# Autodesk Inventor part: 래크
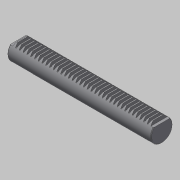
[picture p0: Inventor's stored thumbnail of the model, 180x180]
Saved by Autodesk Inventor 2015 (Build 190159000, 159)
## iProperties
Created: 2019-06
Part Number: 래크
Material: 스테인리스강
Document SubType Name: Modeling
Designer: mduedu
Density: 1 g/cm^3
Appearance: 기본값
Author: mduedu
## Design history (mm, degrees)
sketch "스케치1"
  geometry: L1 (0, 0)-(240, 0); L2 (240, 0)-(240, 34); L3 (240, 34)-(0, 34); L4 (0, 34)-(0, 0)
  constraints: 8 end point, 2 parallel, 1 horizontal, 1 perpendicular
  dimensions: "d0" = 240 distance of L1.start L1.end; "d1" = 34 distance of L1.end L2.end
extrude "돌출1" new body sketch "스케치1" stored distance "d2" = 36; taper "d3" = 0 deg
sketch "스케치2"
  geometry: L1 (0, 0)-(240, 0) reference; L2 (240, 0)-(240, 34) reference; L3 (240, 34)-(0, 34) reference; L4 (0, 34)-(0, 0) reference; L5 (9.44, 29.5)-(10.76, 29.5); L6 (12.398, 34)-(7.802, 34); L7 (10.1, 34)-(10.1, 29.5); L8 (7.802, 34)-(9.44, 29.5); L9 (12.398, 34)-(10.76, 29.5); L10 (8.53, 32)-(11.67, 32); 1 further point
  constraints: 12 end point, 2 midpoint, 2 point on line, 1 collinear, 1 horizontal, 1 parallel, 1 perpendicular, 1 symmetric about line
  dimensions: "d4" = 20 deg angle of L9 L7; "d5" = 2 distance between parallel lines of L10 L6; "d7" = 4.5 distance between parallel lines of L5 L6 (= 2.25 x d5); "d8" = 3.14 distance of L10.start L10.end; "d9" = 10.1 distance between parallel lines of L4 L7
extrude "돌출2" cut sketch "스케치2" stored distance "d10" = 36; taper "d11" = 0 deg
sketch "스케치3"
  geometry: L1 (235.52, 29.5)-(233.882, 34) reference; L2 (233.882, 34)-(232.198, 34) reference; L3 (232.198, 34)-(230.56, 29.5) reference; L4 (230.56, 29.5)-(229.24, 29.5) reference; L5 (229.24, 29.5)-(227.602, 34) reference; L6 (227.602, 34)-(225.918, 34) reference; L7 (225.918, 34)-(224.28, 29.5) reference; L8 (224.28, 29.5)-(222.96, 29.5) reference; L9 (222.96, 29.5)-(221.322, 34) reference; L10 (221.322, 34)-(219.638, 34) reference; L11 (219.638, 34)-(218, 29.5) reference; L12 (218, 29.5)-(216.68, 29.5) reference; L13 (216.68, 29.5)-(215.042, 34) reference; L14 (215.042, 34)-(213.358, 34) reference; L15 (213.358, 34)-(211.72, 29.5) reference; L16 (211.72, 29.5)-(210.4, 29.5) reference; L17 (210.4, 29.5)-(208.762, 34) reference; L18 (208.762, 34)-(207.078, 34) reference; L19 (207.078, 34)-(205.44, 29.5) reference; L20 (205.44, 29.5)-(204.12, 29.5) reference; L21 (204.12, 29.5)-(202.482, 34) reference; L22 (202.482, 34)-(200.798, 34) reference; L23 (200.798, 34)-(199.16, 29.5) reference; L24 (199.16, 29.5)-(197.84, 29.5) reference; L25 (197.84, 29.5)-(196.202, 34) reference; L26 (196.202, 34)-(194.518, 34) reference; L27 (194.518, 34)-(192.88, 29.5) reference; L28 (192.88, 29.5)-(191.56, 29.5) reference; L29 (191.56, 29.5)-(189.922, 34) reference; L30 (189.922, 34)-(188.238, 34) reference; L31 (188.238, 34)-(186.6, 29.5) reference; L32 (186.6, 29.5)-(185.28, 29.5) reference; L33 (185.28, 29.5)-(183.642, 34) reference; L34 (183.642, 34)-(181.958, 34) reference; L35 (181.958, 34)-(180.32, 29.5) reference; L36 (180.32, 29.5)-(179, 29.5) reference; L37 (179, 29.5)-(177.362, 34) reference; L38 (177.362, 34)-(175.678, 34) reference; L39 (175.678, 34)-(174.04, 29.5) reference; L40 (174.04, 29.5)-(172.72, 29.5) reference; L41 (172.72, 29.5)-(171.082, 34) reference; L42 (171.082, 34)-(169.398, 34) reference; L43 (169.398, 34)-(167.76, 29.5) reference; L44 (167.76, 29.5)-(166.44, 29.5) reference; L45 (166.44, 29.5)-(164.802, 34) reference; L46 (164.802, 34)-(163.118, 34) reference; L47 (163.118, 34)-(161.48, 29.5) reference; L48 (161.48, 29.5)-(160.16, 29.5) reference; L49 (160.16, 29.5)-(158.522, 34) reference; L50 (158.522, 34)-(156.838, 34) reference; L51 (156.838, 34)-(155.2, 29.5) reference; L52 (155.2, 29.5)-(153.88, 29.5) reference; L53 (153.88, 29.5)-(152.242, 34) reference; L54 (152.242, 34)-(150.558, 34) reference; L55 (150.558, 34)-(148.92, 29.5) reference; L56 (148.92, 29.5)-(147.6, 29.5) reference; L57 (147.6, 29.5)-(145.962, 34) reference; L58 (145.962, 34)-(144.278, 34) reference; L59 (144.278, 34)-(142.64, 29.5) reference; L60 (142.64, 29.5)-(141.32, 29.5) reference; L61 (141.32, 29.5)-(139.682, 34) reference; L62 (139.682, 34)-(137.998, 34) reference; L63 (137.998, 34)-(136.36, 29.5) reference; L64 (136.36, 29.5)-(135.04, 29.5) reference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; 1 further point
  constraints: 16 end point, 4 parallel, 2 horizontal, 2 perpendicular
extrude "돌출3" cut sketch "스케치3" stored distance "d18" = 36; taper "d19" = 0 deg
sketch "스케치4"
  geometry: L1 (4.48, 29.5)-(0, 29.5) reference; L2 (0, 29.5)-(0, 0) reference; L3 (0, 0)-(240, 0) reference; L4 (240, 0)-(240, 29.5) reference; L5 (240, 29.5)-(235.52, 29.5) reference; L6 (235.52, 29.5)-(233.882, 34) reference; L7 (233.882, 34)-(232.198, 34) reference; L8 (232.198, 34)-(230.56, 29.5) reference; L9 (230.56, 29.5)-(229.24, 29.5) reference; L10 (229.24, 29.5)-(227.602, 34) reference; L11 (227.602, 34)-(225.918, 34) reference; L12 (225.918, 34)-(224.28, 29.5) reference; L13 (224.28, 29.5)-(222.96, 29.5) reference; L14 (222.96, 29.5)-(221.322, 34) reference; L15 (221.322, 34)-(219.638, 34) reference; L16 (219.638, 34)-(218, 29.5) reference; L17 (218, 29.5)-(216.68, 29.5) reference; L18 (216.68, 29.5)-(215.042, 34) reference; L19 (215.042, 34)-(213.358, 34) reference; L20 (213.358, 34)-(211.72, 29.5) reference; L21 (211.72, 29.5)-(210.4, 29.5) reference; L22 (210.4, 29.5)-(208.762, 34) reference; L23 (208.762, 34)-(207.078, 34) reference; L24 (207.078, 34)-(205.44, 29.5) reference; L25 (205.44, 29.5)-(204.12, 29.5) reference; L26 (204.12, 29.5)-(202.482, 34) reference; L27 (202.482, 34)-(200.798, 34) reference; L28 (200.798, 34)-(199.16, 29.5) reference; L29 (199.16, 29.5)-(197.84, 29.5) reference; L30 (197.84, 29.5)-(196.202, 34) reference; L31 (196.202, 34)-(194.518, 34) reference; L32 (194.518, 34)-(192.88, 29.5) reference; L33 (192.88, 29.5)-(191.56, 29.5) reference; L34 (191.56, 29.5)-(189.922, 34) reference; L35 (189.922, 34)-(188.238, 34) reference; L36 (188.238, 34)-(186.6, 29.5) reference; L37 (186.6, 29.5)-(185.28, 29.5) reference; L38 (185.28, 29.5)-(183.642, 34) reference; L39 (183.642, 34)-(181.958, 34) reference; L40 (181.958, 34)-(180.32, 29.5) reference; L41 (180.32, 29.5)-(179, 29.5) reference; L42 (179, 29.5)-(177.362, 34) reference; L43 (177.362, 34)-(175.678, 34) reference; L44 (175.678, 34)-(174.04, 29.5) reference; L45 (174.04, 29.5)-(172.72, 29.5) reference; L46 (172.72, 29.5)-(171.082, 34) reference; L47 (171.082, 34)-(169.398, 34) reference; L48 (169.398, 34)-(167.76, 29.5) reference; L49 (167.76, 29.5)-(166.44, 29.5) reference; L50 (166.44, 29.5)-(164.802, 34) reference; L51 (164.802, 34)-(163.118, 34) reference; L52 (163.118, 34)-(161.48, 29.5) reference; L53 (161.48, 29.5)-(160.16, 29.5) reference; L54 (160.16, 29.5)-(158.522, 34) reference; L55 (158.522, 34)-(156.838, 34) reference; L56 (156.838, 34)-(155.2, 29.5) reference; L57 (155.2, 29.5)-(153.88, 29.5) reference; L58 (153.88, 29.5)-(152.242, 34) reference; L59 (152.242, 34)-(150.558, 34) reference; L60 (150.558, 34)-(148.92, 29.5) reference; L61 (148.92, 29.5)-(147.6, 29.5) reference; L62 (147.6, 29.5)-(145.962, 34) reference; L63 (145.962, 34)-(144.278, 34) reference; L64 (144.278, 34)-(142.64, 29.5) reference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; 1 further point
  constraints: 8 end point, 2 parallel, 1 horizontal, 1 perpendicular, 1 point on line
  dimensions: "d20" = 36 distance between parallel lines of L156 L2; "d21" = 10 distance between parallel lines of L4 L154; "d22" = 194 distance between parallel lines of L154 L156 (derived); "d23" = 4 distance between parallel lines of L3 L155
extrude "돌출4" cut sketch "스케치4" stored distance "d24" = 36; taper "d25" = 0 deg
sketch "스케치5"
  geometry: L1 (36, 0)-(0, 0) reference; C1 r 18 at (18, 18); 2 further points
  constraints: 1 centre point, 1 midpoint, 1 tangent, 1 vertical alignment
  dimensions: "d26" = 36 diameter of C1
extrude "돌출5" sketch "스케치5" stored distance "d27" = 36; taper "d28" = 0 deg
chamfer "모따기1" distance "d29" = 1; stored, may be unused: second distance "d30" = 2, angle "d31" = 45 deg
node "솔리드1"
pattern_linear "직사각형 패턴1" dims "d14" = 6.28, "d17" = 6.28
node "투영된 루프1"
node "투영된 루프2"
node "투영된 루프3"
